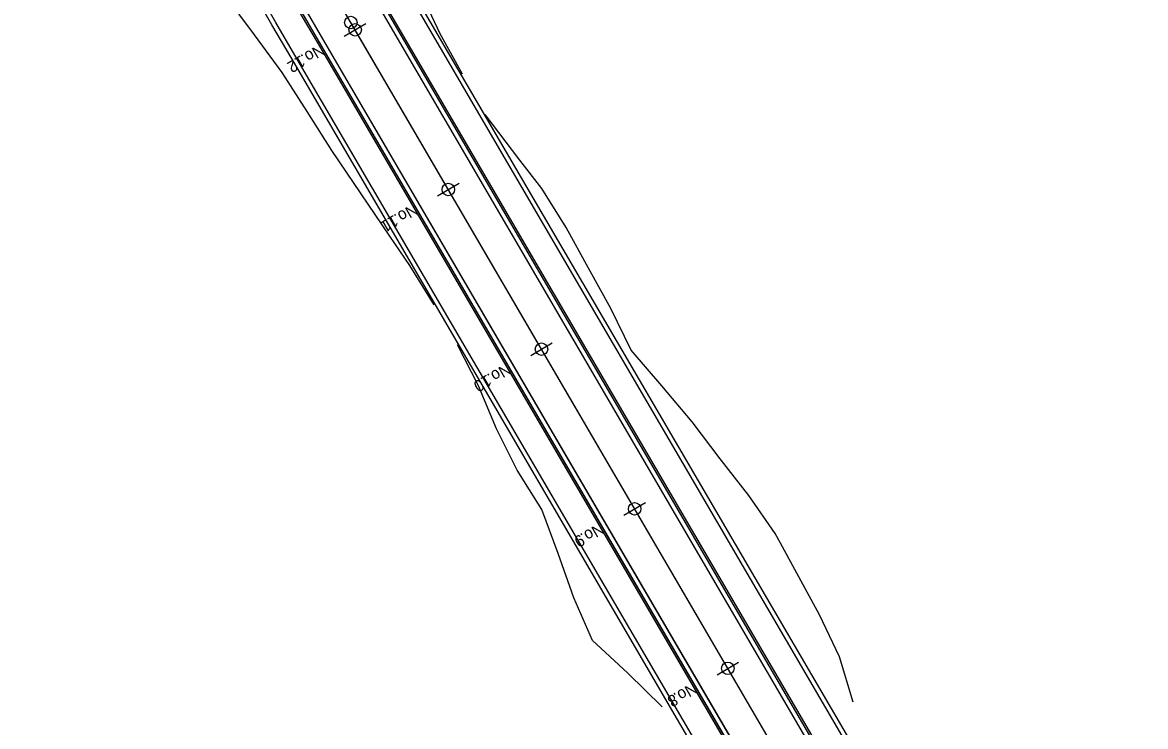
# Model space of a CAD drawing. Extents: x 46424 to 47578, y 10417 to 11548.
# Drawn here: x 46423.8 to 46545.4, y 10562.5 to 10638.7 of the extents above; entities that cross this region are included whole.
import ezdxf

# ---------------------------------------------------------------- set-up
doc = ezdxf.new("R2010")
doc.units = 0
for name, color, linetype in [('Default', 7, 'Continuous'), ('出典（地理院地図Vector）', 7, 'Continuous'), ('河川_人工水路(地下)（地理院地図Vector）', 7, 'Continuous'), ('現況_地形', 7, 'Continuous'), ('現況_地形_三角形', 7, 'Continuous'), ('現況_地形_三角形_頂点', 7, 'Continuous'), ('現況_地形_低い点', 7, 'Continuous'), ('現況_地形_単点標高', 7, 'Continuous'), ('現況_地形_等高線_マイナー', 7, 'Continuous'), ('等高線等深線_等高線_補助曲線通常部（地理院地図Vector）', 7, 'Continuous'), ('設計図面_測点 ラベル メジャー', 7, 'Continuous'), ('設計図面_測点 印 メジャー', 7, 'Continuous')]:
    doc.layers.add(name, color=color, linetype=linetype)

msp = doc.modelspace()

# ---------------------------------------------------------------- linework, layer by layer
at = {"layer": 'Default'}
for p, q in [((46516.96, 10540.04), (46459.34, 10638.67)), ((46459.81, 10637.87), (46459.81, 10637.87)), ((46469.9, 10620.6), (46469.9, 10620.6)), ((46479.98, 10603.33), (46479.98, 10603.33)), ((46490.07, 10586.06), (46490.07, 10586.06)), ((46500.16, 10568.8), (46500.16, 10568.8))]:
    msp.add_line(p, q, dxfattribs=at)
for centre in [(46459.34, 10638.67), (46459.81, 10637.87), (46469.9, 10620.6), (46479.98, 10603.33), (46490.07, 10586.06), (46500.16, 10568.8)]:
    msp.add_circle(centre, 0.675, dxfattribs=at)
at = {"layer": '出典（地理院地図Vector）'}
for points in [[(46521.77, 10546.67), (46465.82, 10642.45), (46463.78, 10645.96), (46462.5, 10648.17), (46461.33, 10650.22), (46459.33, 10653.83), (46458.99, 10654.46), (46456.79, 10658.7), (46456.4, 10659.48), (46454.76, 10662.95), (46453.79, 10665.16), (46452.94, 10667.22), (46451.59, 10670.88), (46451.37, 10671.52), (46450.09, 10675.84), (46449.88, 10676.64)], [(46508.82, 10539.11), (46452.87, 10634.89), (46450.8, 10638.43), (46449.49, 10640.7), (46448.27, 10642.84), (46446.15, 10646.68), (46445.78, 10647.36), (46443.37, 10651.99), (46442.94, 10652.86), (46441.1, 10656.76), (46439.99, 10659.29), (46439, 10661.69), (46437.4, 10666.01), (46437.14, 10666.78), (46435.57, 10672.05), (46435.32, 10673.03)]]:
    msp.add_lwpolyline(points, dxfattribs=at)
at = {"layer": '河川_人工水路(地下)（地理院地図Vector）'}
msp.add_line((46516.96, 10540.04), (46459.34, 10638.67), dxfattribs=at)
at = {"layer": '現況_地形'}
for points in [[(46518.31, 10544.66), (46462.37, 10640.43), (46460.32, 10643.95), (46459.03, 10646.18), (46457.85, 10648.25), (46455.82, 10651.92), (46455.47, 10652.56), (46453.21, 10656.91), (46452.81, 10657.71), (46451.12, 10661.3), (46450.11, 10663.59), (46449.23, 10665.75), (46447.81, 10669.58), (46447.58, 10670.26), (46446.22, 10674.83), (46446, 10675.68)], [(46518.32, 10544.66), (46462.38, 10640.44), (46460.33, 10643.95), (46459.04, 10646.18), (46457.86, 10648.26), (46455.83, 10651.92), (46455.48, 10652.57), (46453.22, 10656.91), (46452.82, 10657.72), (46451.13, 10661.3), (46450.12, 10663.6), (46449.24, 10665.75), (46447.82, 10669.59), (46447.59, 10670.26), (46446.23, 10674.83), (46446.01, 10675.68)], [(46512.26, 10541.12), (46456.31, 10636.9), (46454.25, 10640.43), (46452.95, 10642.69), (46451.75, 10644.8), (46449.66, 10648.58), (46449.3, 10649.25), (46446.94, 10653.77), (46446.52, 10654.62), (46444.73, 10658.41), (46443.66, 10660.85), (46442.71, 10663.16), (46441.18, 10667.31), (46440.93, 10668.04), (46439.43, 10673.06), (46439.2, 10673.99)], [(46512.27, 10541.13), (46456.32, 10636.9), (46454.26, 10640.44), (46452.96, 10642.69), (46451.76, 10644.81), (46449.66, 10648.58), (46449.3, 10649.25), (46446.95, 10653.78), (46446.53, 10654.62), (46444.74, 10658.41), (46443.67, 10660.86), (46442.72, 10663.17), (46441.18, 10667.31), (46440.94, 10668.05), (46439.44, 10673.06), (46439.21, 10674)]]:
    msp.add_lwpolyline(points, dxfattribs=at)
at = {"layer": '現況_地形_三角形'}
for points in [[(46468.38, 10608.14), (46465.72, 10612.37), (46463.56, 10615.55), (46457.3, 10624.83), (46454.61, 10629.05), (46451.91, 10633.26), (46448.91, 10637.33), (46447.34, 10639.47), (46445.88, 10641.49), (46443.3, 10645.13), (46442.84, 10645.77), (46439.74, 10650.18), (46439.18, 10651.01), (46436.78, 10654.81), (46435.52, 10657.4), (46434.49, 10659.9), (46432.81, 10664.44), (46432.54, 10665.25), (46430.88, 10670.82), (46430.62, 10671.87)], [(46471.44, 10633.09), (46469.01, 10637.45), (46466.87, 10642)]]:
    msp.add_lwpolyline(points, dxfattribs=at)
at = {"layer": '現況_地形_三角形_頂点'}
for points in [[(46513.71, 10565.13), (46512.24, 10570.06), (46510.08, 10574.59), (46505.86, 10582.35), (46505.3, 10583.38), (46502.42, 10587.49), (46499.34, 10591.48), (46496.28, 10595.48), (46493.01, 10599.36), (46489.71, 10603.22), (46487.51, 10607.73), (46485.06, 10612.09), (46482.66, 10616.48), (46480.01, 10620.72), (46477.65, 10623.77), (46473.88, 10628.72)], [(46493.05, 10564.64), (46489.35, 10568.27), (46486.4, 10570.98), (46485.5, 10571.81), (46483.49, 10576.43), (46481.78, 10581.22), (46480.02, 10585.98), (46477.37, 10590.22), (46475.13, 10594.71), (46473.16, 10599.35), (46470.88, 10603.81)]]:
    msp.add_lwpolyline(points, dxfattribs=at)
at = {"layer": '現況_地形_低い点'}
for points in [[(46518.75, 10544.91), (46462.8, 10640.69), (46460.75, 10644.2), (46459.47, 10646.42), (46458.29, 10648.5), (46456.26, 10652.16), (46455.91, 10652.8), (46453.66, 10657.13), (46453.26, 10657.94), (46451.57, 10661.51), (46450.57, 10663.79), (46449.69, 10665.93), (46448.28, 10669.74), (46448.05, 10670.42), (46446.7, 10674.96), (46446.49, 10675.8)], [(46511.84, 10540.87), (46455.89, 10636.65), (46453.83, 10640.19), (46452.53, 10642.44), (46451.32, 10644.56), (46449.23, 10648.34), (46448.86, 10649.01), (46446.5, 10653.56), (46446.08, 10654.4), (46444.29, 10658.21), (46443.21, 10660.66), (46442.25, 10662.98), (46440.71, 10667.15), (46440.46, 10667.89), (46438.96, 10672.93), (46438.72, 10673.87)]]:
    msp.add_lwpolyline(points, dxfattribs=at)
at = {"layer": '現況_地形_単点標高'}
for points in [[(46521.34, 10546.42), (46465.39, 10642.2), (46463.35, 10645.71), (46462.07, 10647.92), (46460.9, 10649.97), (46458.89, 10653.59), (46458.55, 10654.22), (46456.34, 10658.47), (46455.95, 10659.26), (46454.31, 10662.74), (46453.33, 10664.96), (46452.48, 10667.04), (46451.12, 10670.72), (46450.9, 10671.36), (46449.6, 10675.72), (46449.4, 10676.52)], [(46518.92, 10545.01), (46462.97, 10640.79), (46460.92, 10644.3), (46459.64, 10646.52), (46458.46, 10648.59), (46456.43, 10652.25), (46456.09, 10652.9), (46453.84, 10657.22), (46453.44, 10658.02), (46451.76, 10661.59), (46450.75, 10663.87), (46449.88, 10666.01), (46448.47, 10669.81), (46448.24, 10670.48), (46446.89, 10675.01), (46446.68, 10675.85)], [(46511.67, 10540.77), (46455.72, 10636.55), (46453.66, 10640.08), (46452.35, 10642.34), (46451.15, 10644.47), (46449.05, 10648.25), (46448.69, 10648.92), (46446.33, 10653.47), (46445.9, 10654.32), (46444.1, 10658.12), (46443.02, 10660.58), (46442.07, 10662.91), (46440.52, 10667.08), (46440.27, 10667.83), (46438.77, 10672.88), (46438.53, 10673.83)], [(46509.25, 10539.36), (46453.3, 10635.14), (46451.24, 10638.68), (46449.92, 10640.95), (46448.71, 10643.09), (46446.59, 10646.91), (46446.22, 10647.59), (46443.82, 10652.21), (46443.39, 10653.08), (46441.55, 10656.97), (46440.45, 10659.49), (46439.47, 10661.88), (46437.87, 10666.18), (46437.62, 10666.94), (46436.06, 10672.17), (46435.81, 10673.15)]]:
    msp.add_lwpolyline(points, dxfattribs=at)
at = {"layer": '現況_地形_等高線_マイナー'}
for points in [[(46518.76, 10544.92), (46462.82, 10640.7), (46460.77, 10644.21), (46459.48, 10646.43), (46458.3, 10648.51), (46456.28, 10652.17), (46455.93, 10652.81), (46453.68, 10657.14), (46453.28, 10657.94), (46451.59, 10661.51), (46450.59, 10663.8), (46449.71, 10665.94), (46448.3, 10669.75), (46448.07, 10670.42), (46446.72, 10674.96), (46446.5, 10675.8)], [(46511.82, 10540.86), (46455.87, 10636.64), (46453.81, 10640.18), (46452.51, 10642.43), (46451.3, 10644.55), (46449.21, 10648.34), (46448.85, 10649), (46446.49, 10653.55), (46446.07, 10654.39), (46444.27, 10658.2), (46443.19, 10660.65), (46442.24, 10662.97), (46440.69, 10667.14), (46440.44, 10667.88), (46438.94, 10672.93), (46438.7, 10673.87)]]:
    msp.add_lwpolyline(points, dxfattribs=at)
at = {"layer": '等高線等深線_等高線_補助曲線通常部（地理院地図Vector）'}
for p, q in [((46545.38, 10491.38), (46423.8, 10699.52)), ((46516.96, 10540.04), (46459.34, 10638.67))]:
    msp.add_line(p, q, dxfattribs=at)
at = {"layer": '設計図面_測点 印 メジャー'}
for p, q in [((46458.64, 10637.19), (46460.97, 10638.55)), ((46468.73, 10619.92), (46471.06, 10621.28)), ((46478.82, 10602.65), (46481.15, 10604.01)), ((46488.91, 10585.38), (46491.24, 10586.75)), ((46498.99, 10568.11), (46501.33, 10569.48))]:
    msp.add_line(p, q, dxfattribs=at)

# ---------------------------------------------------------------- texts
at = {"layer": '設計図面_測点 ラベル メジャー'}
for s, p in [('No.', (46456.04, 10636.4)), ('12', (46453.94, 10635.17)), ('No.', (46466.13, 10619.13)), ('11', (46464.02, 10617.9)), ('No.', (46476.22, 10601.86)), ('10', (46474.11, 10600.63)), ('No.', (46486.3, 10584.59)), ('9', (46484.2, 10583.36)), ('No.', (46496.39, 10567.32)), ('8', (46494.29, 10566.09))]:
    msp.add_text(s, height=1.25, rotation=210.291, dxfattribs=at).set_placement(p)

doc.saveas('drawing.dxf')
